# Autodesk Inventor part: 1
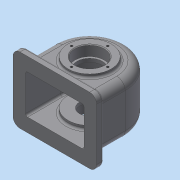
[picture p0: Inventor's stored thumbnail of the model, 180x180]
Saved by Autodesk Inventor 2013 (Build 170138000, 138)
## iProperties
Created: 2018-07
Part Number: 1
Material: 일반
Document SubType Name: Modeling
Designer: Administrator
Density: 1 g/cm^3
Author: Administrator
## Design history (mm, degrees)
sketch "스케치1"
  geometry: L1 (-51, 0)-(51, 0); L2 (51, 0)-(51, 101); L3 (51, 101)-(-51, 101); L4 (-51, 101)-(-51, 0); 2 further points
  constraints: 8 end point, 2 parallel, 1 coincident, 1 horizontal, 1 midpoint, 1 perpendicular
  dimensions: "d0" = 101 distance of L3.end L1.start; "d2" = 102 distance of L2.end L3.end
extrude "돌출1" new body sketch "스케치1" stored distance "d3" = 74; taper "d4" = 0 deg
fillet "모깎기1" dims "d5" = 51
fillet "모깎기2" dims "d6" = 12
feature "쉘1" dims "d7" = 9
sketch "스케치2"
  geometry: L1 (78, 0)-(0, 0) reference; L2 (90, 12)-(90, 62) reference; L3 (0, 74)-(78, 74) reference; L4 (-12, 62)-(-12, 12) reference; L5 (-21, 84.5)-(99, 84.5); L6 (99, 84.5)-(99, -10.5); L7 (99, -10.5)-(-21, -10.5); L8 (-21, -10.5)-(-21, 84.5); A1 r 12 centre (0, 12) between (-12, 12) and (0, 0) reference; A2 r 12 centre (78, 12) between (78, 0) and (90, 12) reference; A3 r 12 centre (78, 62) between (90, 62) and (78, 74) reference; A4 r 12 centre (0, 62) between (0, 74) and (-12, 62) reference; 3 further points
  constraints: 8 end point, 2 midpoint, 2 parallel, 1 horizontal, 1 horizontal alignment, 1 perpendicular, 1 vertical alignment
  dimensions: "d8" = 120 distance of L5.start L5.end; "d10" = 95 distance of L5.end L6.end
extrude "돌출2" join sketch "스케치2" distance "d11" = 10; taper "d12" = 0 deg
fillet "모깎기3" dims "d13" = 10
node "작업 평면1"
sketch "스케치3"
  geometry: L1 (-50, 0)-(50, 0) reference; C1 r 31 at (0, 50); 2 further points
  constraints: 1 centre point, 1 midpoint, 1 vertical alignment
  dimensions: "d15" = 62 diameter of C1; "d16" = 50 distance from line of L1 C1.centre
extrude "돌출3" join sketch "스케치3" distance "d17" = 20; taper "d18" = 0 deg
hole "구멍1" diameter "d21" = 36; stored, may be unused: countersink angle "d25" = 90 deg, drill point angle "d27" = 118 deg; dims "d19" = 10, "d20" = 10, "d22" = 6, "d23" = 42, "d24" = 15, "d26" = 8
hole "구멍2" diameter "d30" = 29; stored, may be unused: countersink angle "d34" = 90 deg, drill point angle "d36" = 118 deg; dims "d28" = 10, "d29" = 10, "d31" = 6, "d32" = 35, "d33" = 15, "d35" = 8
sketch "스케치4"
  geometry: C1 r 17.5 at (0, 0) reference; 2 further points
  constraints: 1 vertical alignment
  dimensions: "d37" = 26 distance of C1.centre point (0, 26)
hole "구멍3" sketch "스케치4" at (0, 26) diameter "d38" = 3.242; stored, may be unused: countersink angle "d42" = 90 deg, drill point angle "d44" = 118 deg; dims "d39" = 8, "d40" = 35, "d41" = 15, "d43" = 10
fillet "모깎기4" dims "d48" = 3
fillet "모깎기5" dims "d49" = 3
chamfer "모따기1" distance "d50" = 1; stored, may be unused: second distance "d51" = 2, angle "d52" = 45 deg
fillet "모깎기6" dims "d53" = 3
fillet "모깎기7" dims "d54" = 3
fillet "모깎기8" dims "d55" = 3
node "솔리드1"
mirror "대칭1"
pattern_circular "원형 패턴1" dims angle "d46" = 360 deg
mirror "대칭2"
other parameters: "d14" = 42
